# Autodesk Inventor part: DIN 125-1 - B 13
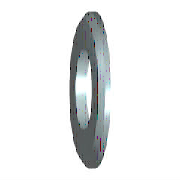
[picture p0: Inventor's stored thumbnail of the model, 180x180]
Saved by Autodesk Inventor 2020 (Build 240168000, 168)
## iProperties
Created: 2010-02
Part Number: DIN 125-1 - B 13
Material: Stahl, weich, unlegiert
Document SubType Name: Modeling
Standard: DIN 125-1
Designer: DLutz
Standards Organization: DIN
Language: de-DE
Size Designation: B 13
Categories: <MemberInstance><Categories><Category DisplayName="Verbindungselemente" InternalName="e4da775c-781d-43d5-af7c-5136215cf5a6" Mnemonic="FSTN"><Category DisplayNam
Mass: 6.16752 g
Surface Area: 9.01799 cm^2
Volume: 0.784672 cm^3
Density: 7.86 g/cm^3
Appearance: Metall - Stahl
IsCustomPart: 0
Author: DLutz
Revision Number: C
Title: Unterlegscheibe
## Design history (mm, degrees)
chamfer "Chamfer" distance "d4" = 0.625 (= PHH); stored, may be unused: angle "d5" = 45 deg, second distance "d8" = 0.625 (= PHH)
workaxis "Work Axis1"
workplane "Work Plane1"
body "Solid1"
sketch "Sketch"
  geometry: C1 r 12 at (0, 0); C2 r 6.5 at (0, 0); 1 further point
  constraints: 2 centre point, 2 coincident
  dimensions: "d0" = 13 diameter of C2 (= SD1); "d1" = 24 diameter of C1 (= SD2)
extrude "Body" new body sketch "Sketch" distance "d2" = 2.5 (= SD); taper "d3" = 0 deg
other parameters: "SD1" = 13 [user parameter; used in 1 equation term], "SD2" = 24 [user parameter; used in 1 equation term], "SD" = 2.5 [user parameter; used in 1 equation term], "PHH" = 0.625 [user parameter; used in 2 equation terms], "FAWI" = 45 deg [user parameter], "d6" = 0, "d7" = 0, "d9" = 0, "d10" = 0, "NND" = 12 [user parameter]
